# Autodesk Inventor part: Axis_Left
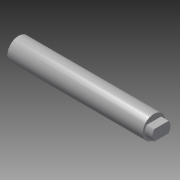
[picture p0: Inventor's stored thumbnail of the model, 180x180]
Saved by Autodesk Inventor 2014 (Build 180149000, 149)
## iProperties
Created: 2006-03
Part Number: Axis_Left
Document SubType Name: Modeling
Designer: debonom
Material: Stainless Steel, 440C
Mass: 126.377 g
Surface Area: 47.6763 cm^2
Volume: 16.3066 cm^3
Density: 7.75 g/cm^3
Appearance: Steel
Author: debonom
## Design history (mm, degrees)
sketch "Sketch1"
  geometry: L1 (-4.823, 3.575)-(4.823, 3.575); L2 (4.823, 3.575)-(4.823, -3.575); L3 (4.823, -3.575)-(-4.822, -3.575); L4 (-4.822, -3.575)-(-4.823, 3.575); L5 (-4.823, 3.575)-(4.823, -3.575); L6 (-8.405, 0)-(8.405, 0) reference; A1 r 6 centre (-0.004, 0) between (-4.823, 3.575) and (-4.822, -3.575); A2 r 6 centre (0.004, 0) between (4.823, -3.575) and (4.823, 3.575); 2 further points
  constraints: 10 end point, 4 point on circle, 2 centre point, 2 parallel, 2 point on line, 1 coincident, 1 equal radius, 1 horizontal, 1 midpoint, 1 perpendicular
  dimensions: "d0" = 9.645 distance of L2.end L3.end; "d1" = 7.15 distance of L3.end L1.start; "d2" = 6 radius of A1
extrude "Extrusion1" new body sketch "Sketch1" distance "d3" = 5; taper "d4" = 0 deg
sketch "Sketch2"
  geometry: C1 r 7.5 at (0, 0); 1 further point
  constraints: 1 centre point, 1 coincident
  dimensions: "d5" = 15 diameter of C1
extrude "Extrusion2" join sketch "Sketch2" distance "d6" = 90; taper "d7" = 0 deg
body "Solid1"
